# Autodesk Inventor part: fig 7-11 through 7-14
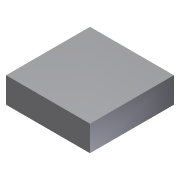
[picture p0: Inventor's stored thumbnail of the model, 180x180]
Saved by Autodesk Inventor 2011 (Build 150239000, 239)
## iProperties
Created: 2009-09
Part Number: fig 7-11 through 7-14
Document SubType Name: Modeling
Designer: Sham
Density: 1 g/cm^3
Author: Sham
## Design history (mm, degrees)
sketch "Sketch1"
  geometry: L1 (-23, 20)-(0, 20); L2 (0, 20)-(0, -3); L3 (0, -3)-(-23, -3); L4 (-23, -3)-(-23, 20)
  constraints: 8 end point, 2 parallel, 1 horizontal, 1 perpendicular
  dimensions: "d2" = 23 distance of L1.start L1.end; "d3" = 23 distance of L3.end L1.start
extrude "Extrusion1" new body sketch "Sketch1" distance "d0" = 7; taper "d1" = 0 deg
body "Solid1"
